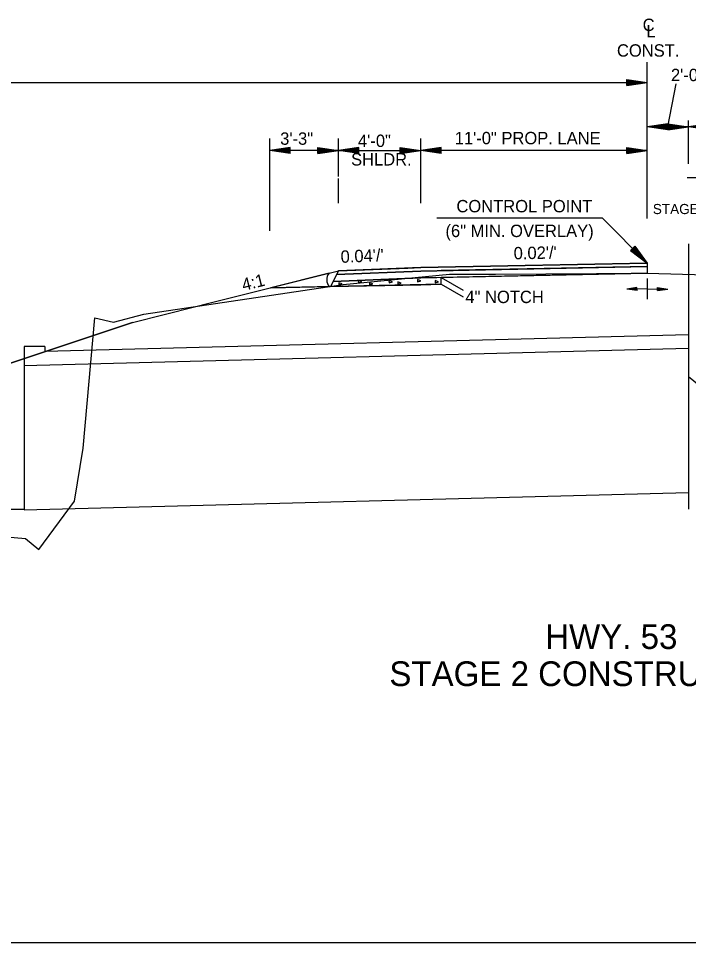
# Model space of a CAD drawing. Extents: x 2829243 to 2838161, y 467639 to 474695.
# Drawn here: x 2830081.2 to 2830406.5, y 469069.4 to 469517.8 of the extents above; entities that cross this region are included whole.
import ezdxf

# ---------------------------------------------------------------- set-up
doc = ezdxf.new("R2010")
doc.units = 0
for name, color, linetype in [('Default', 7, 'Continuous'), ('R_Dimension', 7, 'Continuous'), ('R_Draft', 7, 'Continuous'), ('R_Exist Surface', 7, 'Continuous'), ('R_Fin Surface', 7, 'Continuous'), ('R_Water', 7, 'Continuous')]:
    doc.layers.add(name, color=color, linetype=linetype)

msp = doc.modelspace()

# ---------------------------------------------------------------- linework, layer by layer
at = {"layer": 'Default'}
msp.add_line((2829486.2, 469069.38), (2831121.84, 469069.38), dxfattribs=at)
at = {"layer": 'R_Dimension'}
for p, q in [((2830386.49, 469420.83), (2830386.49, 469496.67)), ((2829681.3, 469486.75), (2830386.49, 469486.75)), ((2830376.49, 469488.25), (2830386.49, 469486.75)), ((2830376.49, 469485.25), (2830376.49, 469488.25)), ((2830376.49, 469488), (2830384.82, 469486.75)), ((2830376.49, 469487.75), (2830383.1, 469486.75)), ((2830376.49, 469487.5), (2830381.44, 469486.75)), ((2830376.49, 469487.24), (2830379.74, 469486.75)), ((2830376.49, 469486.99), (2830378.07, 469486.75)), ((2830376.49, 469485.25), (2830386.49, 469486.75)), ((2830376.49, 469486.27), (2830379.74, 469486.75)), ((2830376.49, 469485.76), (2830383.1, 469486.75)), ((2830376.49, 469485.5), (2830384.82, 469486.75)), ((2830376.49, 469486.01), (2830381.44, 469486.75)), ((2830376.49, 469486.52), (2830378.07, 469486.75)), ((2830396.49, 469465.24), (2830400.54, 469486.06)), ((2830406.49, 469447.22), (2830406.49, 469468.24)), ((2830396.49, 469466.74), (2830386.49, 469465.24)), ((2830406.49, 469465.24), (2830386.49, 469465.24)), ((2830396.49, 469463.74), (2830386.49, 469465.24)), ((2830396.49, 469466.49), (2830388.16, 469465.24)), ((2830396.49, 469463.99), (2830388.16, 469465.24)), ((2830396.49, 469466.23), (2830389.88, 469465.24)), ((2830396.49, 469464.24), (2830389.88, 469465.24)), ((2830396.49, 469465.98), (2830391.55, 469465.24)), ((2830396.49, 469464.49), (2830391.55, 469465.24)), ((2830396.49, 469465.73), (2830393.24, 469465.24)), ((2830396.49, 469464.75), (2830393.24, 469465.24)), ((2830396.49, 469465.47), (2830394.91, 469465.24)), ((2830396.49, 469465), (2830394.91, 469465.24)), ((2830396.49, 469466.74), (2830406.49, 469465.24)), ((2830396.49, 469463.74), (2830396.49, 469466.74)), ((2830396.49, 469463.74), (2830396.49, 469466.74)), ((2830396.49, 469466.49), (2830404.82, 469465.24)), ((2830396.49, 469466.23), (2830403.1, 469465.24)), ((2830396.49, 469465.98), (2830401.44, 469465.24)), ((2830396.49, 469465.73), (2830399.74, 469465.24)), ((2830396.49, 469465.47), (2830398.07, 469465.24)), ((2830396.49, 469463.74), (2830406.49, 469465.24)), ((2830396.49, 469464.75), (2830399.74, 469465.24)), ((2830396.49, 469464.24), (2830403.1, 469465.24)), ((2830396.49, 469463.99), (2830404.82, 469465.24)), ((2830396.49, 469464.49), (2830401.44, 469465.24)), ((2830396.49, 469465), (2830398.07, 469465.24)), ((2830416.49, 469466.74), (2830406.49, 469465.24)), ((2830446.49, 469465.24), (2830406.49, 469465.24)), ((2830416.49, 469463.74), (2830406.49, 469465.24)), ((2830203.16, 469414.71), (2830203.16, 469459.54)), ((2830236.49, 469441.21), (2830236.49, 469459.54)), ((2830276.49, 469428.23), (2830276.49, 469459.54)), ((2830213.16, 469455.29), (2830203.16, 469453.79)), ((2830213.16, 469455.04), (2830204.83, 469453.79)), ((2830213.16, 469454.79), (2830206.55, 469453.79)), ((2830213.16, 469452.29), (2830213.16, 469455.29)), ((2830226.49, 469455.29), (2830236.49, 469453.79)), ((2830226.49, 469452.29), (2830226.49, 469455.29)), ((2830226.49, 469455.04), (2830234.82, 469453.79)), ((2830226.49, 469454.79), (2830233.1, 469453.79)), ((2830246.49, 469455.29), (2830236.49, 469453.79)), ((2830246.49, 469455.04), (2830238.16, 469453.79)), ((2830246.49, 469454.79), (2830239.88, 469453.79)), ((2830246.49, 469452.29), (2830246.49, 469455.29)), ((2830266.49, 469455.29), (2830276.49, 469453.79)), ((2830266.49, 469452.29), (2830266.49, 469455.29)), ((2830266.49, 469455.04), (2830274.82, 469453.79)), ((2830266.49, 469454.79), (2830273.1, 469453.79)), ((2830286.49, 469455.29), (2830276.49, 469453.79)), ((2830286.49, 469455.04), (2830278.16, 469453.79)), ((2830286.49, 469454.79), (2830279.88, 469453.79)), ((2830286.49, 469452.29), (2830286.49, 469455.29)), ((2830376.49, 469455.29), (2830386.49, 469453.79)), ((2830376.49, 469452.29), (2830376.49, 469455.29)), ((2830376.49, 469455.04), (2830384.82, 469453.79)), ((2830376.49, 469454.79), (2830383.1, 469453.79)), ((2830213.16, 469452.29), (2830203.16, 469453.79)), ((2830236.49, 469453.79), (2830203.72, 469453.79)), ((2830213.16, 469452.54), (2830204.83, 469453.79)), ((2830213.16, 469452.8), (2830206.55, 469453.79)), ((2830213.16, 469454.54), (2830208.22, 469453.79)), ((2830213.16, 469453.05), (2830208.22, 469453.79)), ((2830213.16, 469454.28), (2830209.91, 469453.79)), ((2830213.16, 469453.31), (2830209.91, 469453.79)), ((2830213.16, 469454.03), (2830211.58, 469453.79)), ((2830213.16, 469453.56), (2830211.58, 469453.79)), ((2830226.49, 469454.54), (2830231.44, 469453.79)), ((2830226.49, 469454.28), (2830229.74, 469453.79)), ((2830226.49, 469454.03), (2830228.07, 469453.79)), ((2830226.49, 469452.29), (2830236.49, 469453.79)), ((2830226.49, 469453.31), (2830229.74, 469453.79)), ((2830226.49, 469452.8), (2830233.1, 469453.79)), ((2830226.49, 469452.54), (2830234.82, 469453.79)), ((2830226.49, 469453.05), (2830231.44, 469453.79)), ((2830226.49, 469453.56), (2830228.07, 469453.79)), ((2830236.49, 469453.79), (2830276.49, 469453.79)), ((2830246.49, 469452.29), (2830236.49, 469453.79)), ((2830246.49, 469452.54), (2830238.16, 469453.79)), ((2830246.49, 469452.8), (2830239.88, 469453.79)), ((2830246.49, 469454.54), (2830241.55, 469453.79)), ((2830246.49, 469453.05), (2830241.55, 469453.79)), ((2830246.49, 469454.28), (2830243.24, 469453.79)), ((2830246.49, 469453.31), (2830243.24, 469453.79)), ((2830246.49, 469454.03), (2830244.91, 469453.79)), ((2830246.49, 469453.56), (2830244.91, 469453.79)), ((2830266.49, 469454.54), (2830271.44, 469453.79)), ((2830266.49, 469454.28), (2830269.74, 469453.79)), ((2830266.49, 469454.03), (2830268.07, 469453.79)), ((2830266.49, 469452.29), (2830276.49, 469453.79)), ((2830266.49, 469453.31), (2830269.74, 469453.79)), ((2830266.49, 469452.8), (2830273.1, 469453.79)), ((2830266.49, 469452.54), (2830274.82, 469453.79)), ((2830266.49, 469453.05), (2830271.44, 469453.79)), ((2830266.49, 469453.56), (2830268.07, 469453.79)), ((2830386.49, 469453.79), (2830276.49, 469453.79)), ((2830286.49, 469452.29), (2830276.49, 469453.79)), ((2830286.49, 469452.54), (2830278.16, 469453.79)), ((2830286.49, 469452.8), (2830279.88, 469453.79)), ((2830286.49, 469454.54), (2830281.55, 469453.79)), ((2830286.49, 469453.05), (2830281.55, 469453.79)), ((2830286.49, 469454.28), (2830283.24, 469453.79)), ((2830286.49, 469453.31), (2830283.24, 469453.79)), ((2830286.49, 469454.03), (2830284.91, 469453.79)), ((2830286.49, 469453.56), (2830284.91, 469453.79)), ((2830376.49, 469454.54), (2830381.44, 469453.79)), ((2830376.49, 469454.28), (2830379.74, 469453.79)), ((2830376.49, 469454.03), (2830378.07, 469453.79)), ((2830376.49, 469452.29), (2830386.49, 469453.79)), ((2830376.49, 469453.31), (2830379.74, 469453.79)), ((2830376.49, 469452.8), (2830383.1, 469453.79)), ((2830376.49, 469452.54), (2830384.82, 469453.79)), ((2830376.49, 469453.05), (2830381.44, 469453.79)), ((2830376.49, 469453.56), (2830378.07, 469453.79)), ((2830236.49, 469428.23), (2830236.49, 469440.1)), ((2830466.54, 469440.5), (2830405.78, 469440.5)), ((2830364.75, 469420.9), (2830284.24, 469420.9)), ((2830386.49, 469399.15), (2830364.75, 469420.9)), ((2830378.36, 469405.16), (2830380.48, 469407.28)), ((2830378.54, 469405.34), (2830385.31, 469400.33)), ((2830378.72, 469405.52), (2830384.1, 469401.55)), ((2830378.9, 469405.7), (2830382.92, 469402.73)), ((2830379.08, 469405.88), (2830381.72, 469403.92)), ((2830379.26, 469406.06), (2830380.54, 469405.11)), ((2830379.59, 469406.39), (2830380.54, 469405.11)), ((2830379.77, 469406.57), (2830381.72, 469403.92)), ((2830379.95, 469406.75), (2830382.92, 469402.73)), ((2830380.13, 469406.93), (2830384.1, 469401.55)), ((2830380.31, 469407.11), (2830385.31, 469400.33)), ((2830380.48, 469407.28), (2830386.49, 469399.15)), ((2830378.36, 469405.16), (2830386.49, 469399.15)), ((2830276.49, 469396.95), (2830236.49, 469395.35)), ((2830386.49, 469399.15), (2830276.49, 469396.95)), ((2830276.49, 469395.25), (2830386.49, 469397.45)), ((2830386.49, 469397.45), (2830276.49, 469395.25)), ((2830386.49, 469399.15), (2830386.49, 469399.15)), ((2830386.49, 469399.15), (2830386.49, 469399.15)), ((2830386.49, 469397.45), (2830386.49, 469397.45)), ((2830386.49, 469397.45), (2830386.49, 469397.45)), ((2830386.49, 469397.45), (2830386.49, 469397.45)), ((2830386.49, 469397.45), (2830386.49, 469397.45)), ((2830386.49, 469397.45), (2830386.49, 469397.45)), ((2830231.96, 469394.22), (2830203.72, 469387.16)), ((2830235.63, 469393.62), (2830233.94, 469390.25)), ((2830233.94, 469390.25), (2830276.49, 469391.95)), ((2830276.49, 469391.95), (2830233.94, 469390.25)), ((2830236.49, 469395.35), (2830235.63, 469393.62)), ((2830235.63, 469393.62), (2830276.49, 469395.25)), ((2830276.49, 469395.25), (2830235.63, 469393.62)), ((2830276.49, 469391.95), (2830386.49, 469394.15)), ((2830386.49, 469394.15), (2830386.49, 469394.15)), ((2830386.49, 469394.15), (2830386.49, 469394.15)), ((2830386.49, 469394.15), (2830386.49, 469394.15)), ((2830203.72, 469387.16), (2830232.08, 469387.73)), ((2830233.94, 469390.25), (2830232.69, 469387.74)), ((2830232.69, 469387.74), (2830276.49, 469388.61)), ((2830386.49, 469391.61), (2830386.49, 469381.61)), ((2830386.49, 469391.61), (2830386.49, 469381.61)), ((2830381.48, 469387.26), (2830376.49, 469386.41)), ((2830381.48, 469387.26), (2830376.49, 469386.41)), ((2830386.49, 469386.61), (2830376.49, 469386.41)), ((2830386.49, 469386.61), (2830376.49, 469386.41)), ((2830381.51, 469385.76), (2830376.49, 469386.41)), ((2830381.51, 469385.76), (2830376.49, 469386.41)), ((2830381.48, 469387.13), (2830377.33, 469386.43)), ((2830381.48, 469387.13), (2830377.33, 469386.43)), ((2830381.5, 469385.88), (2830377.33, 469386.43)), ((2830381.5, 469385.88), (2830377.33, 469386.43)), ((2830381.48, 469387.01), (2830378.19, 469386.44)), ((2830381.48, 469387.01), (2830378.19, 469386.44)), ((2830381.5, 469386.01), (2830378.19, 469386.44)), ((2830381.5, 469386.01), (2830378.19, 469386.44)), ((2830381.48, 469386.88), (2830379.02, 469386.46)), ((2830381.48, 469386.88), (2830379.02, 469386.46)), ((2830381.5, 469386.14), (2830379.02, 469386.46)), ((2830381.5, 469386.14), (2830379.02, 469386.46)), ((2830381.49, 469386.75), (2830379.87, 469386.48)), ((2830381.49, 469386.75), (2830379.87, 469386.48)), ((2830381.5, 469386.27), (2830379.87, 469386.48)), ((2830381.5, 469386.27), (2830379.87, 469386.48)), ((2830381.49, 469386.63), (2830380.7, 469386.49)), ((2830381.49, 469386.63), (2830380.7, 469386.49)), ((2830381.49, 469386.39), (2830380.7, 469386.49)), ((2830381.49, 469386.39), (2830380.7, 469386.49)), ((2830381.51, 469385.76), (2830381.48, 469387.26)), ((2830381.51, 469385.76), (2830381.48, 469387.26)), ((2830386.49, 469386.61), (2830396.49, 469386.41)), ((2830386.49, 469386.61), (2830396.49, 469386.41)), ((2830391.48, 469385.76), (2830391.51, 469387.26)), ((2830391.48, 469385.76), (2830391.51, 469387.26)), ((2830391.48, 469386.01), (2830394.8, 469386.44)), ((2830391.48, 469386.01), (2830394.8, 469386.44)), ((2830391.48, 469385.88), (2830395.66, 469386.43)), ((2830391.48, 469385.88), (2830395.66, 469386.43)), ((2830391.48, 469385.76), (2830396.49, 469386.41)), ((2830391.48, 469385.76), (2830396.49, 469386.41)), ((2830391.49, 469386.39), (2830392.28, 469386.49)), ((2830391.49, 469386.39), (2830392.28, 469386.49)), ((2830391.49, 469386.27), (2830393.12, 469386.48)), ((2830391.49, 469386.27), (2830393.12, 469386.48)), ((2830391.49, 469386.14), (2830393.97, 469386.46)), ((2830391.49, 469386.14), (2830393.97, 469386.46)), ((2830391.5, 469387.01), (2830394.8, 469386.44)), ((2830391.5, 469387.01), (2830394.8, 469386.44)), ((2830391.5, 469386.88), (2830393.97, 469386.46)), ((2830391.5, 469386.88), (2830393.97, 469386.46)), ((2830391.5, 469386.75), (2830393.12, 469386.48)), ((2830391.5, 469386.75), (2830393.12, 469386.48)), ((2830391.5, 469386.63), (2830392.28, 469386.49)), ((2830391.5, 469386.63), (2830392.28, 469386.49)), ((2830391.51, 469387.26), (2830396.49, 469386.41)), ((2830391.51, 469387.26), (2830396.49, 469386.41)), ((2830391.51, 469387.13), (2830395.66, 469386.43)), ((2830391.51, 469387.13), (2830395.66, 469386.43)), ((2830406.49, 469344.05), (2830429.42, 469325.27))]:
    msp.add_line(p, q, dxfattribs=at)
msp.add_lwpolyline([(2830276.49, 469388.61), (2830286.49, 469388.81), (2830286.49, 469392.15), (2830276.49, 469391.95)], dxfattribs=at)
msp.add_arc((2830235.88, 469391.04), 5.04, 140.9001, 221.1293, dxfattribs=at)
at = {"layer": 'R_Draft'}
for p, q in [((2830406.49, 469408.41), (2830406.49, 469279.68)), ((2830386.49, 469399.15), (2830276.49, 469396.95)), ((2830386.49, 469397.45), (2830286.49, 469395.45)), ((2830386.49, 469399.15), (2830386.49, 469394.15)), ((2830386.49, 469394.15), (2830286.49, 469392.15)), ((2830286.49, 469392.15), (2830297.07, 469386.05)), ((2830286.49, 469388.81), (2830203.72, 469387.16)), ((2830286.49, 469388.81), (2830297.07, 469382.71)), ((2830136.49, 469370.35), (2829681.3, 469218.66))]:
    msp.add_line(p, q, dxfattribs=at)
for points in [[(2830238.37, 469389), (2830236.71, 469389.6), (2830236.75, 469388.5), (2830238.37, 469389)], [(2830247.85, 469390.06), (2830246.19, 469390.67), (2830246.24, 469389.57), (2830247.85, 469390.06)], [(2830253.26, 469389), (2830251.6, 469389.6), (2830251.64, 469388.5), (2830253.26, 469389)], [(2830262.74, 469390.06), (2830261.08, 469390.67), (2830261.13, 469389.57), (2830262.74, 469390.06)], [(2830267.03, 469389.45), (2830265.37, 469390.06), (2830265.41, 469388.96), (2830267.03, 469389.45)], [(2830276.51, 469390.52), (2830274.85, 469391.12), (2830274.9, 469390.02), (2830276.51, 469390.52)], [(2830285.08, 469390.01), (2830283.42, 469390.61), (2830283.46, 469389.51), (2830285.08, 469390.01)]]:
    msp.add_lwpolyline(points, dxfattribs=at)
at = {"layer": 'R_Exist Surface'}
msp.add_line((2830386.49, 469394.15), (2830286.49, 469392.15), dxfattribs=at)
msp.add_lwpolyline([(2829982.69, 469274.29), (2830084.6, 469265.45), (2830091.16, 469260.07), (2830108.46, 469283.54), (2830112.64, 469309.32), (2830118.31, 469372.62), (2830127.4, 469370.46), (2830142, 469374.34), (2830238.91, 469388.67), (2830290.49, 469393.73), (2830312.76, 469393.71), (2830386.29, 469394.15), (2830461.58, 469392.08), (2830487.94, 469391.31), (2830517.3, 469390.3), (2830577.11, 469386.68), (2830580.48, 469385.31), (2830588.89, 469385.2), (2830609.34, 469323.91), (2830618.48, 469295.56), (2830626.4, 469291.95), (2830627.56, 469289.97), (2830768.41, 469271.07)], dxfattribs=at)
at = {"layer": 'R_Fin Surface'}
msp.add_lwpolyline([(2829681.3, 469218.66), (2830136.49, 469370.35), (2830167.36, 469378.07), (2830173.01, 469379.48), (2830226.66, 469392.89), (2830236.49, 469395.35), (2830270.3, 469396.7), (2830276.49, 469396.95), (2830369.45, 469398.81), (2830386.49, 469399.15)], dxfattribs=at)
at = {"layer": 'R_Water'}
for p, q in [((2830093.93, 469356.4), (2830406.49, 469364.47)), ((2830083.93, 469358.67), (2830083.93, 469279.42)), ((2830093.93, 469358.67), (2830083.93, 469358.67)), ((2830083.93, 469349.44), (2830406.49, 469357.77)), ((2830093.93, 469358.67), (2830093.93, 469356.4)), ((2830083.93, 469279.42), (2830406.49, 469287.74)), ((2829864.39, 469279.68), (2830083.93, 469279.68))]:
    msp.add_line(p, q, dxfattribs=at)

# ---------------------------------------------------------------- texts
at = {"layer": 'R_Dimension'}
for s, p in [('C', (2830384.24, 469511.74)), ('L', (2830386.05, 469508.69)), ('CONST.', (2830371.76, 469499.3)), ('2\'-0"', (2830397.98, 469487.42)), ('3\'-3"', (2830208.25, 469456.54)), ('4\'-0"', (2830246.04, 469455.47)), ('11\'-0" PROP. LANE', (2830293, 469456.79)), ('SHLDR.', (2830242.67, 469446.47)), ('CONTROL POINT', (2830293.82, 469423.75)), ('(6" MIN. OVERLAY)', (2830288.5, 469411.75)), ('4" NOTCH', (2830298.18, 469379.72))]:
    msp.add_text(s, height=6, dxfattribs=at).set_placement(p)
for s, rotation, p in [("0.04'/'", 2.2906, (2830237.71, 469399.21)), ("0.02'/'", 1.1458, (2830321.67, 469400.9)), ('4:1', 14.036, (2830190.46, 469385.56))]:
    msp.add_text(s, height=6, rotation=rotation, dxfattribs=at).set_placement(p)
at = {"layer": 'R_Draft'}
for s, height, p in [('STAGE 1: P.C.C.B.', 4.9184, (2830389.17, 469422.9)), ('HWY. 53', 12, (2830336.9, 469211.84)), ('STAGE 2 CONSTRUCTION', 12, (2830261.26, 469193.84))]:
    msp.add_text(s, height=height, dxfattribs=at).set_placement(p)

doc.saveas('drawing.dxf')
